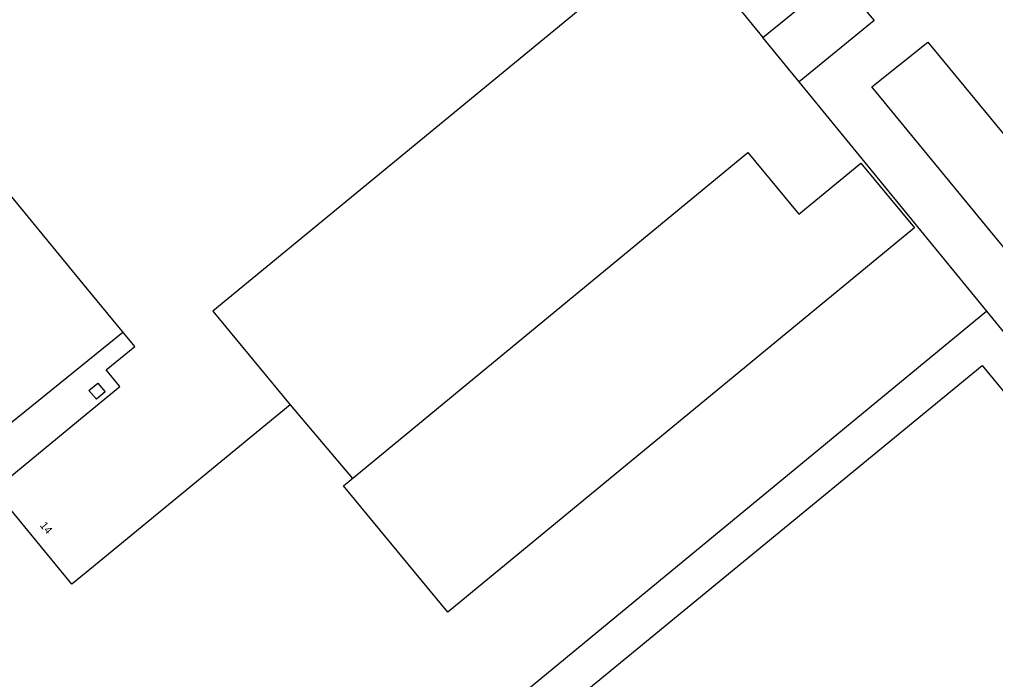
# Model space of a CAD drawing. Extents: x 156141 to 158132, y 385651 to 388399.
# Drawn here: x 156991.7 to 157113.6, y 386567.6 to 386650.1 of the extents above; entities that cross this region are included whole.
import ezdxf

# ---------------------------------------------------------------- set-up
doc = ezdxf.new("R2010")
doc.units = 0
for name, color, linetype in [('IMGEO_Hek', 7, 'Continuous'), ('IMGEO_Lage_trafo', 7, 'Continuous'), ('IMGEO_Pand', 7, 'Continuous'), ('IMGEO_Pand_nummerreeks', 7, 'Continuous'), ('IMGEO_Rijbaan_lokaal_open', 7, 'Continuous'), ('IMGEO_Voetpad_open', 7, 'Continuous')]:
    doc.layers.add(name, color=color, linetype=linetype)

msp = doc.modelspace()

# ---------------------------------------------------------------- linework, layer by layer
at = {"layer": 'IMGEO_Hek'}
for points in [[(156915.96, 386643.49), (156962.48, 386681.55), (156964.52, 386683.22), (157018.84, 386727.99), (157084.51, 386647.83)], [(157112.51, 386613.65), (157010.32, 386529.35)], [(156969.29, 386578.7), (156984.4, 386591.18), (156982.66, 386593.3), (157004.59, 386611.02)], [(157025.46, 386601.92), (157033.25, 386592.71)]]:
    msp.add_lwpolyline(points, dxfattribs=at)
at = {"layer": 'IMGEO_Lage_trafo'}
msp.add_lwpolyline([(157002.37, 386603.53), (157001.27, 386602.62), (157000.35, 386603.73), (157001.46, 386604.64), (157002.37, 386603.53)], dxfattribs=at)
at = {"layer": 'IMGEO_Pand'}
for points in [[(157015.84, 386613.64), (157025.46, 386601.92), (157002.08, 386582.67), (157000, 386580.95), (156998.22, 386579.49), (156988.5, 386591.31), (157000, 386600.76), (157004.2, 386604.21), (157002.5, 386606.28), (157006.07, 386609.22), (157000, 386616.6), (156979.09, 386642.04), (156969.51, 386653.7), (156993.07, 386673.07), (157000, 386664.6), (157008.89, 386653.73), (157039.69, 386679.09), (157049.27, 386667.44), (157062.16, 386651.76), (157015.84, 386613.64)], [(157045.18, 386576), (157041.78, 386580.11), (157032.15, 386591.8), (157082.66, 386633.45), (157089, 386625.77), (157096.77, 386632.13), (157103.44, 386624.04), (157103.27, 386623.9), (157045.18, 386576)], [(157135.47, 386578.26), (157123.98, 386568.81), (157130.53, 386560.85), (157115.81, 386548.73), (157109.24, 386556.7), (157077.52, 386530.62), (157076.75, 386531.56), (157076.55, 386531.8), (157070.84, 386538.71), (157070.64, 386538.98), (157069.93, 386539.82), (157062.44, 386533.65), (157061.47, 386534.83), (157059.76, 386533.43), (157060.65, 386532.22), (157044.43, 386518.9), (157028.49, 386538.25), (157044.71, 386551.57), (157045.68, 386550.4), (157047.45, 386551.87), (157046.48, 386553.04), (157111.92, 386606.86), (157132.44, 386581.94)]]:
    msp.add_lwpolyline(points, dxfattribs=at)
at = {"layer": 'IMGEO_Rijbaan_lokaal_open'}
for points in [[(157093.8, 386655.44), (157098.41, 386649.97), (157089.05, 386642.28)], [(157145.04, 386598.78), (157138.05, 386593.04), (157098.14, 386641.67), (157105.13, 386647.26), (157145.04, 386598.78)], [(157135.98, 386584.94), (157112.51, 386613.65), (157089.05, 386642.28)]]:
    msp.add_lwpolyline(points, dxfattribs=at)
at = {"layer": 'IMGEO_Voetpad_open'}
msp.add_lwpolyline([(157089.05, 386642.28), (157084.51, 386647.83), (157093.8, 386655.44)], dxfattribs=at)

# ---------------------------------------------------------------- texts
at = {"layer": 'IMGEO_Pand_nummerreeks'}
msp.add_text('14', height=1, rotation=309.4254, dxfattribs=at).set_placement((156994.16, 386586.82))

doc.saveas('drawing.dxf')
